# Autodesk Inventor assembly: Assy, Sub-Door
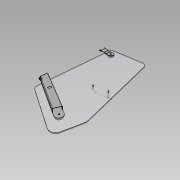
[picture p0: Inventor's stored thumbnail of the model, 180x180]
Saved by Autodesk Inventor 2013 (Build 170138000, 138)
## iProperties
Shininess: 64.0
Length Units: 11269
Angle Units: 11279
Time Units: 11290
Mass Units: 11283
Length Display Precision: 3
Angle Display Precision: 2
Compacted: True
Created: 2005-02
Part Number: Assy, Sub-Door
Document SubType Name: Assembly
Designer: =<Author>
Manufacturer: Standard
Standards Organization: Custom
Description: =<Part Number>
Mass: 10535.8 g
Surface Area: 16971.1 cm^2
Volume: 5677.68 cm^3
Density: 1.85565 g/cm^3
Density: 0.0
Volumn: 0.0
Area: 0.0
PropertySet Name: Model Information
Control State: 0
Master: False
Checked Out: False
Author: PVitaliy
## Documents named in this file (7)
- Y:\Dropbox\Launch 2013\Eco Material Advisor\Assy, Door\_Data\Assy, Cab\Assy, Sub-Door.iam
- Y:\Dropbox\Launch 2013\Eco Material Advisor\Assy, Door\_Data\Assy, Cab\rubber ring.ipt
- Y:\Dropbox\Launch 2013\Eco Material Advisor\Assy, Door\_Data\Assy, Cab\PK46.51.13.003.ipt
- Y:\Dropbox\Launch 2013\Eco Material Advisor\Assy, Door\_Data\Assy, Cab\Handle, Door.ipt
- Y:\Dropbox\Launch 2013\Eco Material Advisor\Assy, Door\_Data\Assy, Cab\Panel, Door.ipt
- Y:\Dropbox\Launch 2013\Eco Material Advisor\Assy, Door\_Data\Assy, Cab\Hinge, Upper.ipt
- Y:\Dropbox\Launch 2013\Eco Material Advisor\Assy, Door\_Data\Assy, Cab\Hinge, Lower.ipt
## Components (13 placed, 6 different names)
1. Panel, Door:1 — Insert:4, Insert:5, Insert:6, Insert:7, Insert:8, Angle:1, Insert:9, Insert:28, Insert:29, Flush:1, Flush:2, Flush:3, Flush:4
2. Hinge, Upper:2 — Insert:1, Angle:1
3. Hinge, Lower:2 — Insert:2, Insert:3
4. Handle, Door:1 — Insert:28, Insert:29, Flush:1, Flush:2, Flush:3, Flush:4
5. rubber ring:1 — Insert:1, Insert:4
6. rubber ring:2 — Insert:5, Insert:10
7. rubber ring:5 — Insert:9, Insert:12
8. rubber ring:6 — Insert:2, Insert:8
9. rubber ring:3 — Insert:3, Insert:6
10. rubber ring:4 — Insert:7, Insert:11
11. PK46.51.13.003:1 — Insert:10
12. PK46.51.13.003:2 — Insert:12
13. PK46.51.13.003:3 — Insert:11
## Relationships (19: Insert 14, Flush 4, Angle 1)
- Insert:1: Hinge, Upper:2 ↔ rubber ring:1
- Insert:2: Hinge, Lower:2 ↔ rubber ring:6
- Insert:3: Hinge, Lower:2 ↔ rubber ring:3
- Insert:4: Panel, Door:1 ↔ rubber ring:1
- Insert:5: Panel, Door:1 ↔ rubber ring:2
- Insert:6: Panel, Door:1 ↔ rubber ring:3
- Insert:7: Panel, Door:1 ↔ rubber ring:4
- Insert:8: Panel, Door:1 ↔ rubber ring:6
- Angle:1: Panel, Door:1 ↔ Hinge, Upper:2
- Insert:9: Panel, Door:1 ↔ rubber ring:5
- Insert:10: rubber ring:2 ↔ PK46.51.13.003:1
- Insert:11: rubber ring:4 ↔ PK46.51.13.003:3
- Insert:12: rubber ring:5 ↔ PK46.51.13.003:2
- Insert:28: Panel, Door:1 ↔ Handle, Door:1
- Insert:29: Panel, Door:1 ↔ Handle, Door:1
- Flush:1: Panel, Door:1 ↔ Handle, Door:1
- Flush:2: Panel, Door:1 ↔ Handle, Door:1
- Flush:3: Panel, Door:1 ↔ Handle, Door:1
- Flush:4: Panel, Door:1 ↔ Handle, Door:1
